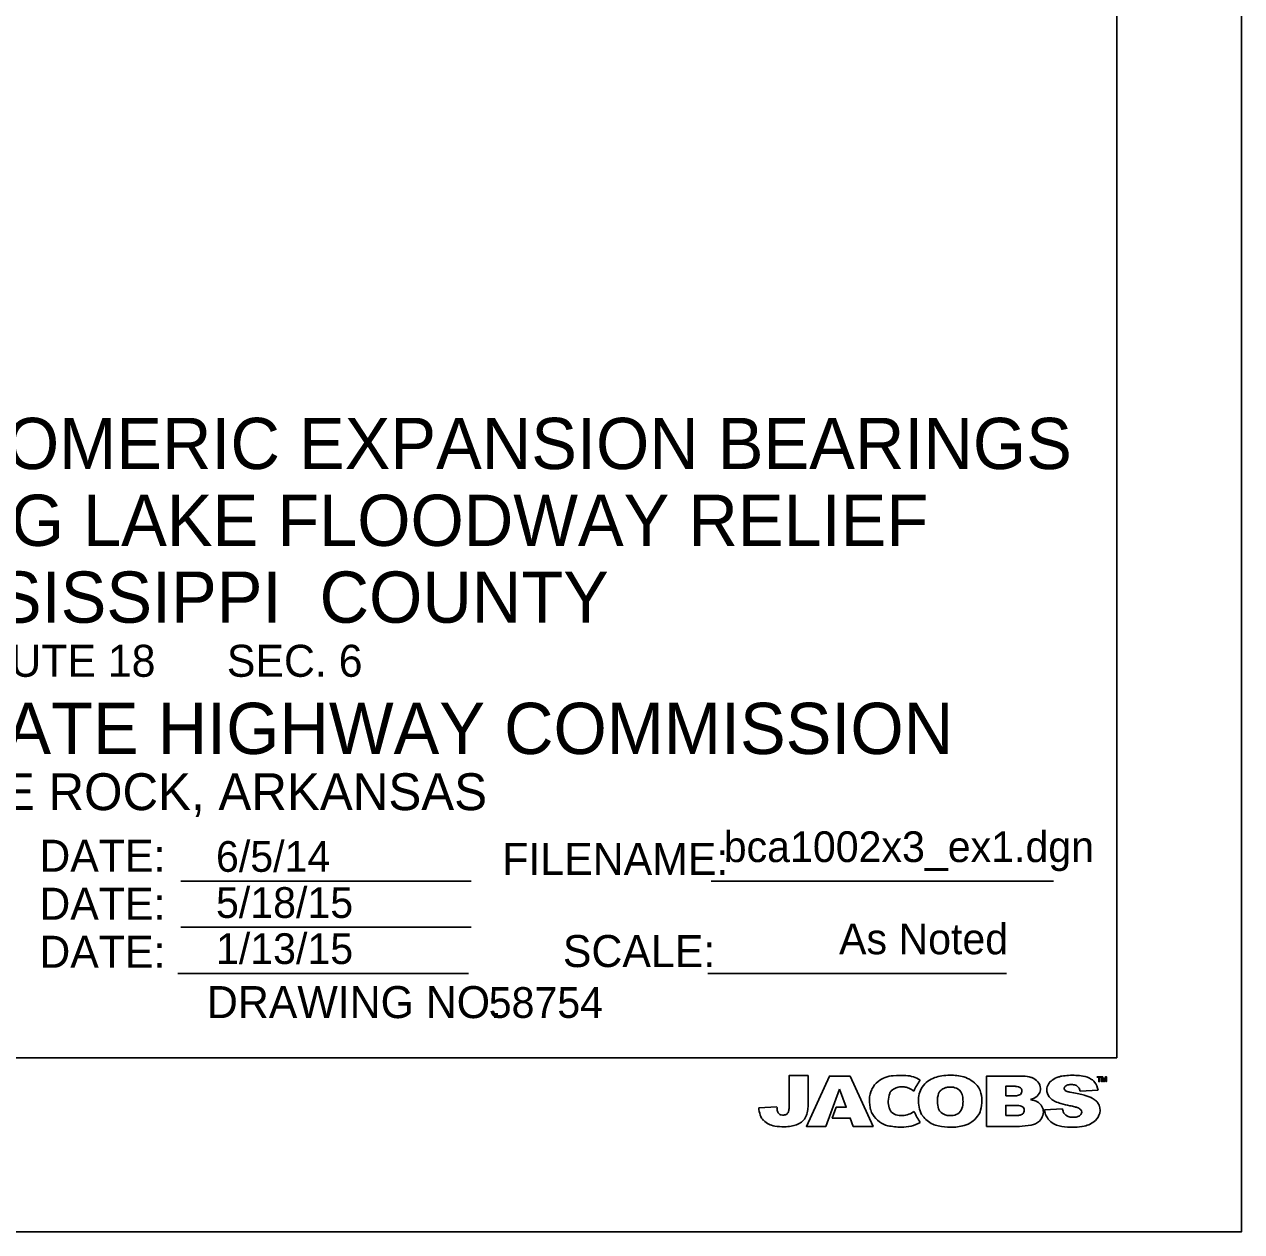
# Model space of a CAD drawing. Extents: x -193 to 149, y 507 to 725.
# Drawn here: x 101.13 to 148.65, y 507.07 to 554.21 of the extents above; entities that cross this region are included whole.
import ezdxf

# ---------------------------------------------------------------- set-up
doc = ezdxf.new("R2010")
doc.units = 0
for name, color, linetype in [('border', 7, 'Continuous'), ('Border 2660-Hwy18 - Level 62', 7, 'Continuous'), ('Border 2660-Hwy18 - Text', 7, 'Continuous'), ('Border 2660-Hwy18 - Title Text', 7, 'Continuous'), ('Text', 7, 'Continuous'), ('Title Block Text', 7, 'Continuous'), ('Title Text', 7, 'Continuous')]:
    doc.layers.add(name, color=color, linetype=linetype)

msp = doc.modelspace()

# ---------------------------------------------------------------- linework, layer by layer
at = {"layer": 'border'}
for p, q in [((143.779, 513.86), (143.779, 719.311)), ((107.239, 520.76), (118.579, 520.76)), ((127.939, 520.76), (141.3, 520.76)), ((107.239, 518.96), (118.579, 518.96)), ((107.131, 517.16), (118.471, 517.16)), ((127.815, 517.16), (139.471, 517.16)), ((143.779, 513.86), (-176.332, 513.86))]:
    msp.add_line(p, q, dxfattribs=at)
for points in [[(131.728, 512.064), (131.728, 513.165), (130.987, 513.165), (130.987, 511.958)], [(132.956, 512.638), (133.216, 511.934), (132.829, 511.934), (132.668, 511.51), (133.37, 511.51), (133.488, 511.186), (134.263, 511.186), (133.367, 513.147), (132.56, 513.147), (131.661, 511.186), (132.417, 511.186), (132.956, 512.638)], [(140.119, 513.147), (138.697, 513.147), (138.697, 511.186)], [(139.768, 512.75), (139.441, 512.75), (139.441, 512.378)], [(143.165, 513.122), (143.014, 513.122), (143.014, 513.104), (143.074, 513.104), (143.074, 512.935), (143.102, 512.935), (143.102, 513.104), (143.165, 513.104), (143.165, 513.122)], [(143.211, 513.092), (143.211, 513.092), (143.271, 512.935), (143.289, 512.935), (143.35, 513.092), (143.35, 513.092), (143.35, 512.935), (143.374, 512.935), (143.374, 513.122), (143.341, 513.122), (143.28, 512.965), (143.22, 513.122), (143.186, 513.122), (143.186, 512.935), (143.211, 512.935), (143.211, 513.092)], [(139.441, 512.378), (139.786, 512.378)], [(142.348, 512.563), (143.047, 512.596)], [(130.512, 511.949), (129.804, 511.912)], [(139.817, 512.003), (139.441, 512.003), (139.441, 511.607)], [(141.659, 511.87), (140.957, 511.834)], [(139.441, 511.607), (139.823, 511.607)], [(138.697, 511.186), (139.974, 511.186)]]:
    msp.add_lwpolyline(points, dxfattribs=at)
for centre, radius, start, end in [((134.948, 512.292), 0.809, 126.8513, 155.2444), ((135.144, 512.03), 1.137, 94.7853, 126.8513), ((135.352, 509.547), 3.629, 86.903, 94.7853), ((135.351, 512.197), 0.529, 91.5073, 110.7655), ((135.368, 511.568), 1.159, 82.6359, 91.5073), ((135.453, 512.228), 0.493, 65.5548, 82.6359), ((135.487, 512.046), 1.126, 56.9246, 86.903), ((138.351, 511.393), 2.758, 144.635, 154.8844), ((137.037, 512.191), 1.003, 148.6249, 181.2859), ((136.825, 512.32), 0.755, 123.8806, 148.6249), ((137.197, 511.767), 1.421, 111.7104, 123.8806), ((137.076, 512.07), 1.094, 96.5371, 111.7104), ((137.388, 509.345), 3.838, 91.9058, 96.5371), ((137.289, 511.826), 0.895, 90.9675, 100.2108), ((137.331, 511.521), 1.661, 73.4477, 92.4253), ((137.278, 512.099), 0.622, 67.077, 90.4218), ((137.485, 512.038), 1.121, 41.1934, 73.4477), ((137.892, 512.395), 0.579, 18.6966, 41.1934), ((139.753, 511.398), 1.352, 86.2098, 89.3498), ((139.808, 512.234), 0.514, 74.8723, 86.2098), ((139.891, 512.541), 0.196, 40.2425, 74.8723), ((140.12, 512.11), 1.036, 72.1885, 90.1477), ((140.252, 512.522), 0.603, 61.4844, 72.1885), ((140.271, 512.556), 0.564, 34.7868, 61.4844), ((140.476, 512.698), 0.315, 16.9455, 34.7868), ((140.341, 512.657), 0.455, 347.0949, 16.9455), ((141.521, 512.596), 0.476, 124.08, 177.6485), ((141.833, 512.135), 1.032, 108.2808, 124.08), ((141.764, 512.345), 0.811, 99.8173, 108.2808), ((142.039, 510.755), 2.425, 93.402, 99.8173), ((141.884, 512.644), 0.16, 146.4706, 165.3108), ((141.824, 512.684), 0.0877, 130.7855, 146.4706), ((141.933, 512.557), 0.256, 97.3055, 130.7855), ((142.046, 510.641), 2.539, 80.6549, 93.402), ((141.989, 512.124), 0.692, 81.3212, 97.3055), ((142.039, 512.453), 0.359, 57.474, 81.3212), ((142.124, 512.585), 0.202, 37.1977, 57.474), ((142.312, 512.262), 0.897, 57.5906, 80.6549), ((142.528, 512.602), 0.494, 39.0736, 57.5906), ((142.436, 512.527), 0.612, 6.4385, 39.0736), ((135.109, 512.217), 0.987, 155.2444, 178.6811), ((135.653, 512.205), 1.532, 178.6811, 194.3912), ((135.894, 512.141), 1.037, 161.2834, 178.6702), ((135.142, 512.396), 0.243, 134.3139, 161.2834), ((135.361, 512.172), 0.556, 110.7655, 134.3139), ((135.166, 511.596), 1.187, 54.6002, 65.5548), ((137.689, 512.164), 0.917, 160.8611, 181.2981), ((137.094, 512.371), 0.287, 136.1177, 160.8611), ((137.261, 512.211), 0.518, 117.7176, 136.1177), ((137.198, 512.331), 0.382, 100.2108, 117.7176), ((137.37, 512.316), 0.386, 24.6274, 67.077), ((137.212, 512.244), 0.56, 2.7442, 24.6274), ((135.28, 512.151), 2.494, 0.0845, 2.7442), ((137.205, 512.162), 1.305, 344.5708, 18.6966), ((139.786, 513.011), 0.633, 270.0363, 284.1438), ((139.892, 512.588), 0.196, 284.1438, 307.8865), ((139.921, 512.551), 0.149, 307.8866, 341.4625), ((139.959, 512.598), 0.108, 21.9604, 40.2425), ((139.878, 512.565), 0.195, 341.4625, 21.9604), ((140.217, 512.958), 0.753, 284.6785, 296.8411), ((140.344, 512.707), 0.471, 296.8412, 329.8182), ((140.485, 512.624), 0.307, 329.8182, 347.0949), ((141.461, 512.598), 0.416, 177.6485, 218.8535), ((141.578, 512.692), 0.566, 218.8535, 233.6549), ((141.715, 512.878), 0.797, 233.6549, 244.7689), ((141.808, 512.664), 0.0815, 165.3108, 208.2887), ((141.88, 512.714), 0.169, 211.7417, 226.6339), ((141.864, 512.697), 0.145, 226.6339, 245.1429), ((142.033, 513.063), 0.549, 245.1429, 260.9806), ((141.196, 507.787), 4.794, 77.5139, 80.9806), ((137.957, 493.163), 19.772, 76.8035, 77.5139), ((142.005, 512.495), 0.351, 11.0051, 37.1977), ((142.099, 510.825), 1.631, 65.6998, 76.8035), ((142.45, 511.604), 0.776, 51.3565, 65.6998), ((131.024, 512.008), 1.226, 184.5698, 198.1069), ((131.115, 511.928), 0.602, 178.2556, 191.4961), ((130.796, 511.863), 0.277, 191.4961, 218.7511), ((130.693, 511.86), 0.285, 325.4171, 349.1575), ((130.195, 511.955), 0.792, 349.1575, 360), ((126.285, 512.662), 5.492, 350.0951, 351.3706), ((130.492, 512.023), 1.237, 351.3706, 1.8291), ((134.734, 511.969), 0.582, 194.3912, 214.1799), ((135.712, 512.145), 0.855, 178.6702, 195.8531), ((135.294, 512.027), 0.421, 195.8531, 214.5369), ((135.267, 512.008), 0.388, 214.5369, 253.1918), ((135.32, 512.521), 0.928, 291.1956, 305.5144), ((139.491, 513.594), 4.066, 206.7197, 213.678), ((137.557, 512.202), 1.523, 181.2859, 193.1956), ((136.74, 512.011), 0.683, 193.1956, 217.7499), ((137.724, 512.165), 0.951, 181.2981, 197.9492), ((137.103, 511.964), 0.299, 197.9492, 222.7741), ((137.232, 512.083), 0.474, 222.7741, 250.1955), ((137.389, 511.987), 0.36, 299.5401, 342.4003), ((136.865, 512.154), 0.91, 342.4003, 0.0845), ((137.79, 512.001), 0.698, 322.6714, 344.5708), ((139.769, 509.534), 2.471, 86.6838, 88.8756), ((139.883, 511.506), 0.497, 75.9314, 86.6838), ((139.924, 511.669), 0.328, 59.6202, 75.9314), ((140.014, 511.823), 0.15, 30.8341, 59.6202), ((139.991, 511.809), 0.177, 337.5037, 30.8341), ((140.247, 511.324), 0.92, 61.0815, 79.9242), ((140.503, 511.788), 0.39, 44.9773, 61.0815), ((140.459, 511.745), 0.452, 342.9845, 44.9773), ((144.718, 512.363), 3.799, 187.9971, 189.0947), ((141.463, 511.842), 0.503, 189.0947, 202.464), ((142.041, 513.571), 1.563, 244.7689, 253.473), ((142.517, 515.173), 3.234, 253.473, 259.8297), ((142.175, 511.948), 0.523, 188.5141, 201.638), ((141.422, 509.071), 2.966, 76.0104, 79.8297), ((141.903, 511.003), 0.974, 67.9593, 76.0104), ((142.17, 511.66), 0.265, 39.9313, 67.9593), ((142.262, 511.738), 0.145, 2.1813, 39.9313), ((142.609, 511.801), 0.523, 36.5162, 51.3565), ((142.639, 511.823), 0.486, 345.1611, 36.5162), ((130.359, 511.791), 0.527, 198.1069, 225.9799), ((130.547, 511.985), 0.797, 225.9799, 261.0714), ((130.708, 511.793), 0.164, 218.7511, 257.488), ((130.747, 511.97), 0.345, 257.488, 275.7834), ((130.756, 511.882), 0.257, 275.7834, 301.6926), ((130.827, 511.768), 0.122, 301.6926, 325.4171), ((130.919, 512.109), 0.931, 279.1616, 305.8646), ((131.122, 511.829), 0.585, 305.8646, 338.7843), ((131.175, 511.808), 0.527, 338.7843, 350.0951), ((135.301, 512.354), 1.268, 214.1799, 231.6615), ((134.989, 511.96), 0.765, 231.6616, 258.686), ((135.378, 512.373), 0.769, 253.1918, 291.1956), ((135.392, 512.609), 1.457, 268.8163, 299.3878), ((137.076, 512.271), 1.109, 217.7499, 244.1703), ((137.243, 512.114), 0.507, 250.1955, 269.1264), ((137.264, 513.518), 1.911, 269.1264, 272.0424), ((137.314, 512.12), 0.512, 272.0424, 299.5401), ((137.546, 512.187), 1.005, 285.9017, 322.6714), ((139.82, 512.647), 1.04, 270.0001, 276.6749), ((139.891, 512.041), 0.43, 276.6749, 293.0645), ((139.99, 511.81), 0.178, 293.0645, 337.5037), ((140.335, 511.833), 0.609, 279.6279, 313.6357), ((140.403, 511.762), 0.511, 313.6357, 342.9845), ((141.812, 511.986), 0.881, 202.464, 215.8926), ((141.602, 511.834), 0.621, 215.8926, 243.2968), ((141.985, 511.873), 0.319, 201.638, 242.3635), ((142.046, 511.988), 0.45, 242.3635, 264.6229), ((142.079, 512.344), 0.806, 264.6229, 273.901), ((142.103, 512.002), 0.464, 273.901, 289.1925), ((142.169, 511.812), 0.263, 289.1925, 322.566), ((142.266, 511.738), 0.141, 322.566, 2.1813), ((142.407, 511.973), 0.772, 295.6144, 314.022), ((142.521, 511.855), 0.608, 314.022, 345.1611), ((130.802, 513.61), 2.441, 261.0714, 269.9405), ((130.801, 512.839), 1.671, 269.9405, 279.1616), ((135.424, 514.132), 2.98, 258.686, 268.8163), ((136.967, 512.046), 0.859, 244.1703, 259.4942), ((137.356, 514.145), 2.993, 259.4942, 268.6426), ((137.328, 512.951), 1.799, 268.6426, 285.9017), ((139.871, 514.565), 3.381, 271.7224, 279.6279), ((141.729, 512.087), 0.904, 243.2968, 257.4598), ((141.995, 513.282), 2.128, 257.4598, 268.8656), ((142.068, 516.964), 5.811, 268.8656, 270.7612), ((142.121, 512.927), 1.774, 270.7612, 282.5001), ((142.269, 512.259), 1.09, 282.5001, 295.6144)]:
    msp.add_arc(centre, radius, start, end, dxfattribs=at)
at = {"layer": 'Border 2660-Hwy18 - Level 62'}
msp.add_lwpolyline([(-192.533, 725.169), (148.651, 725.169), (148.651, 507.073), (-192.533, 507.073)], close=True, dxfattribs=at)

# ---------------------------------------------------------------- texts
at = {"layer": 'Border 2660-Hwy18 - Text'}
for s, p in [('DATE:', (101.719, 521.127)), ('FILENAME:', (119.789, 521.005)), ('DATE:', (101.719, 519.252)), ('DATE:', (101.719, 517.377)), ('SCALE:', (122.155, 517.405)), ('DRAWING NO.', (108.262, 515.412))]:
    msp.add_text(s, height=1.25, dxfattribs=at).set_placement(p)
at = {"layer": 'Border 2660-Hwy18 - Title Text'}
for s, height, p in [('MISSISSIPPI  COUNTY', 1.99999, (95.269, 530.85)), ('ROUTE 18      SEC. 6', 1.25, (98.078, 528.739)), ('ARKANSAS STATE HIGHWAY COMMISSION', 1.99999, (81.666, 525.724)), ('LITTLE ROCK, ARKANSAS', 1.44, (95.227, 523.532))]:
    msp.add_text(s, height=height, dxfattribs=at).set_placement(p)
at = {"layer": 'Text'}
for s, p in [('6/5/14', (108.614, 521.124)), ('5/18/15', (108.614, 519.324)), ('As Noted', (132.936, 517.905)), ('1/13/15', (108.614, 517.524))]:
    msp.add_text(s, height=1.2, dxfattribs=at).set_placement(p)
at = {"layer": 'Title Block Text'}
for s, p in [('bca1002x3_ex1.dgn', (128.434, 521.505)), ('58754', (119.26, 515.42))]:
    msp.add_text(s, height=1.2, dxfattribs=at).set_placement(p)
at = {"layer": 'Title Text'}
for s, p in [('DETAILS OF ELASTOMERIC EXPANSION BEARINGS ', (75.593, 536.85)), ('BRIDGE OVER BIG LAKE FLOODWAY RELIEF', (78.755, 533.85))]:
    msp.add_text(s, height=1.99999, dxfattribs=at).set_placement(p)

doc.saveas('drawing.dxf')
